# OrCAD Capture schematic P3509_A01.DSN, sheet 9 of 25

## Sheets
9 0016_HDMI: size Custom
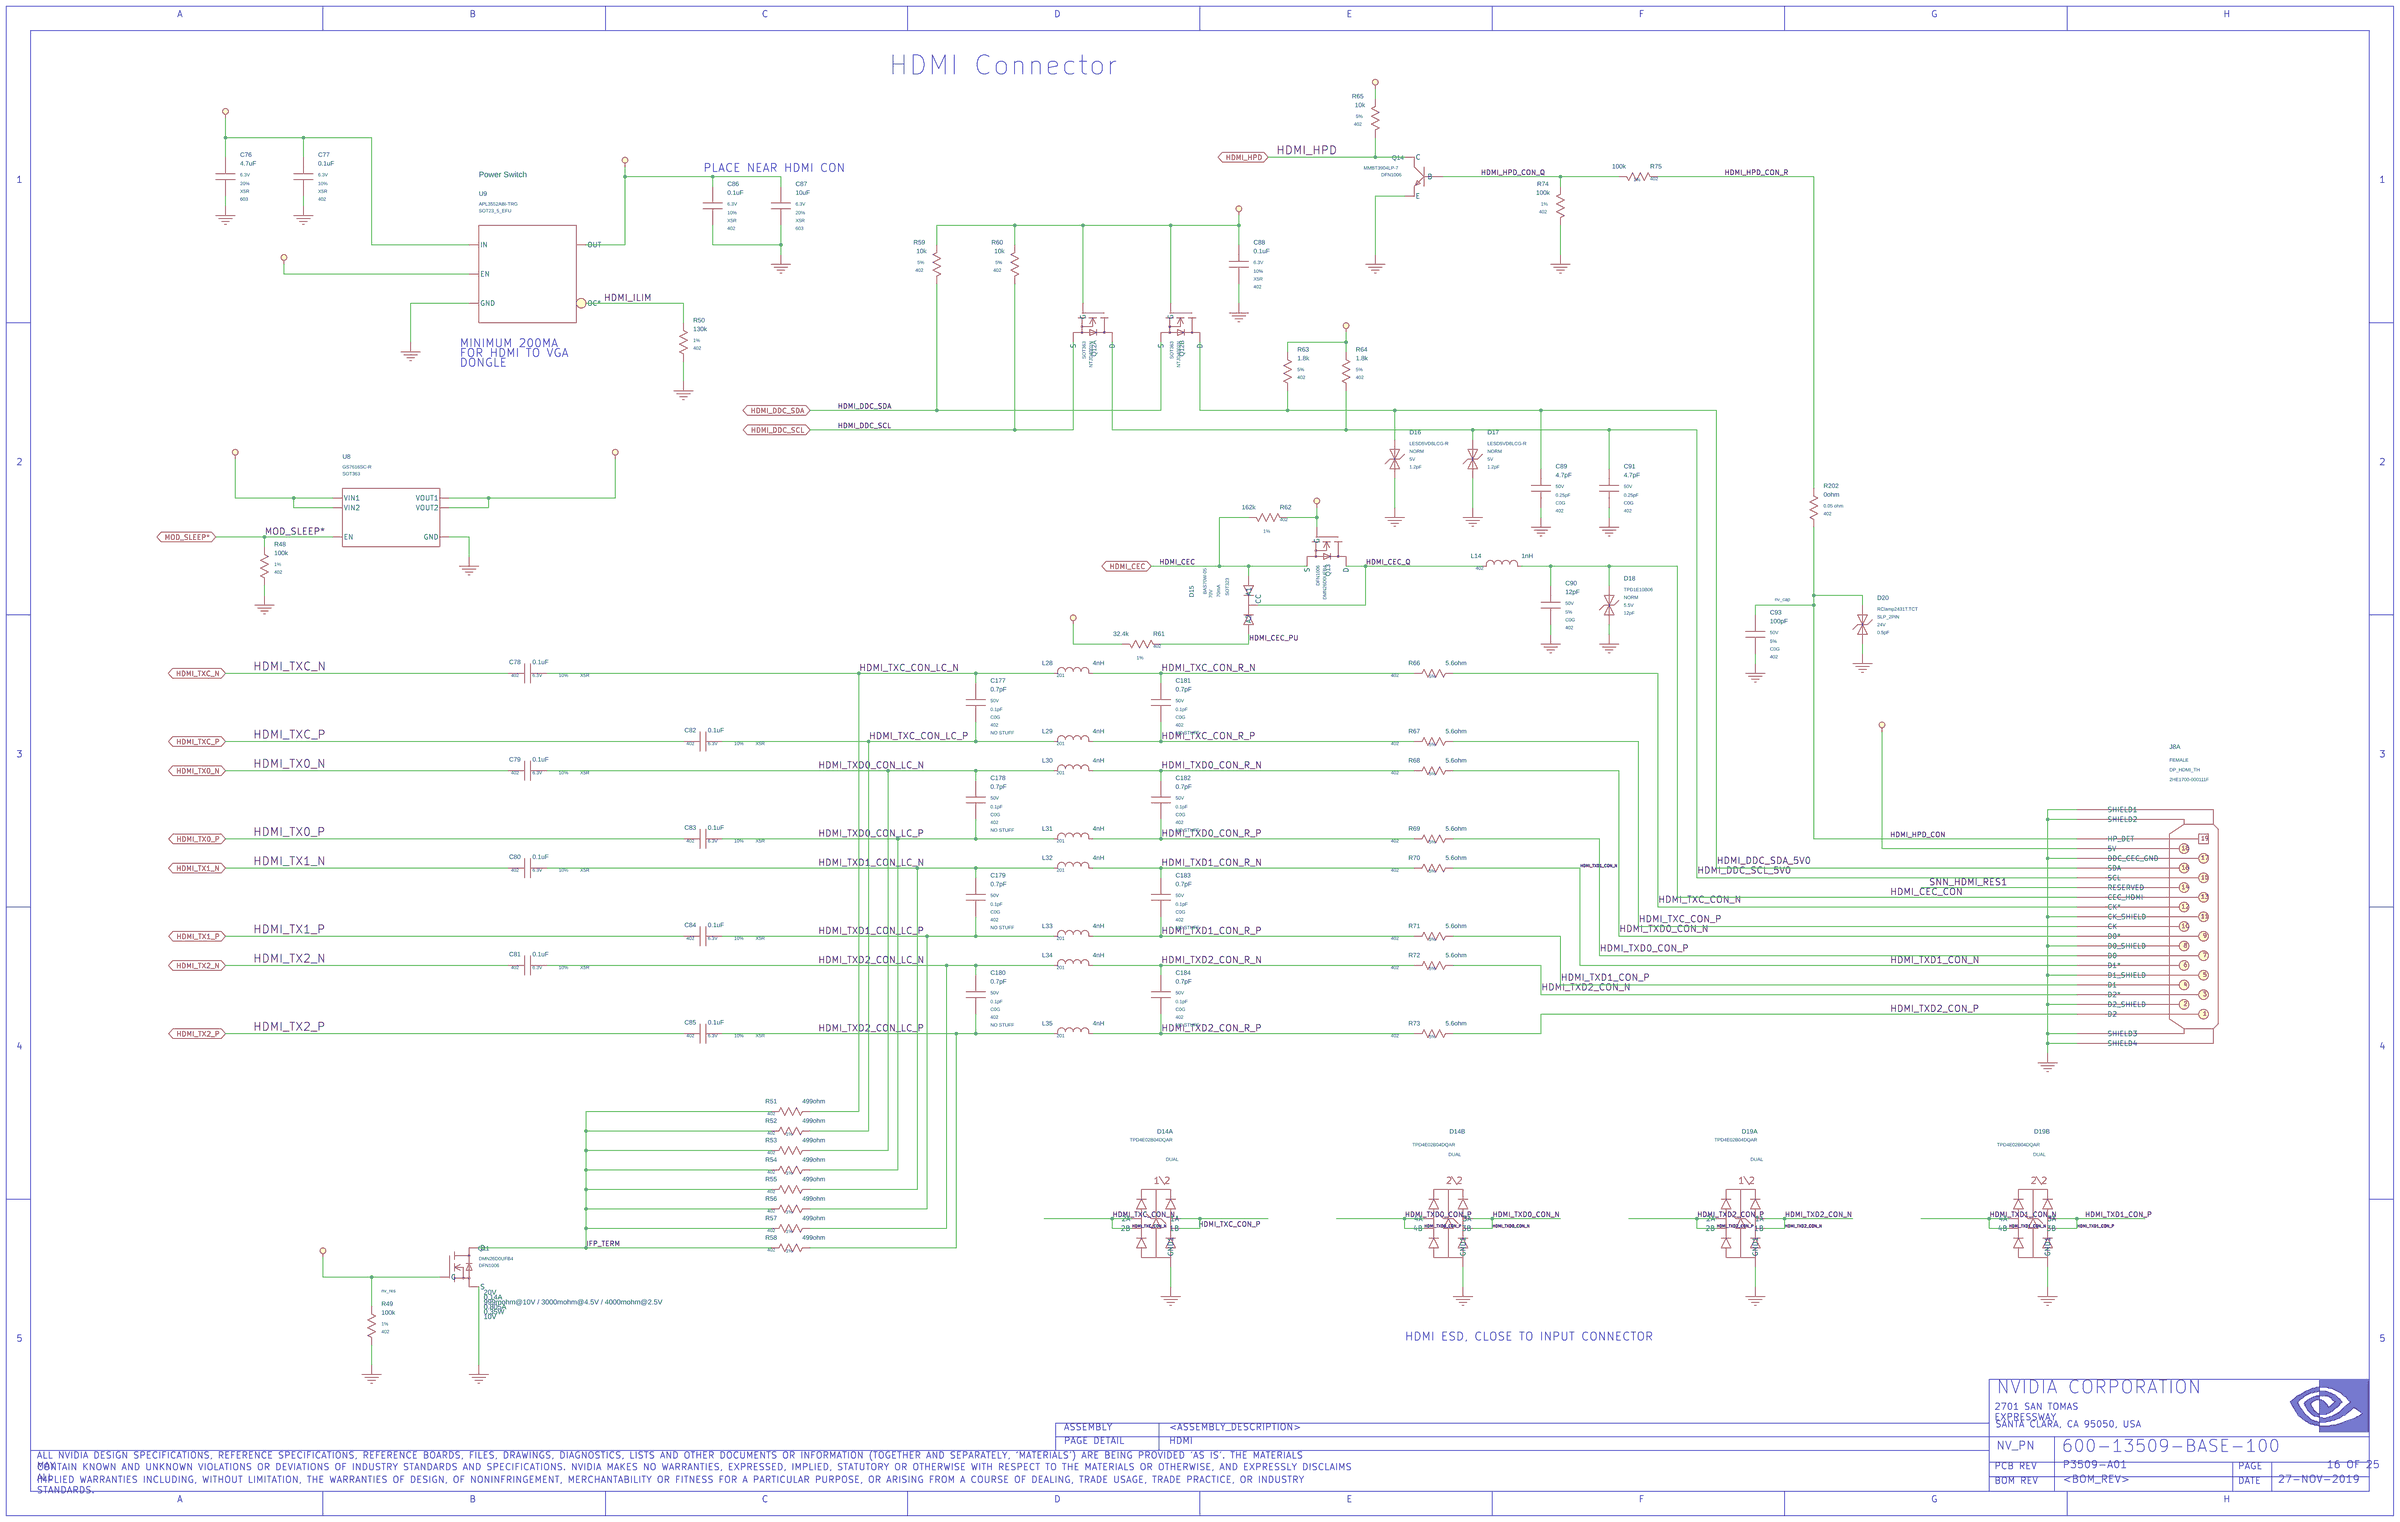
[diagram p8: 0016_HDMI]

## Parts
C76  4.7uF  [603]
C77  0.1uF  [402]
C78  0.1uF  [402]
C79  0.1uF  [402]
C80  0.1uF  [402]
C81  0.1uF  [402]
C82  0.1uF  [402]
C83  0.1uF  [402]
C84  0.1uF  [402]
C85  0.1uF  [402]
C86  0.1uF  [402]
C87  10uF  [603]
C88  0.1uF  [402]
C89  4.7pF  [402]
C90  12pF  [402]
C91  4.7pF  [402]
C93  100pF  [402]
C177  0.7pF  [402]
C178  0.7pF  [402]
C179  0.7pF  [402]
C180  0.7pF  [402]
C181  0.7pF  [402]
C182  0.7pF  [402]
C183  0.7pF  [402]
C184  0.7pF  [402]
D14  D_ESD_DIFFPAIR  [TSLP10_P050_025X010]  (sections A,B)
D15  D_3PIN_CC  [SOT323]
D16  D_ESD  [DIODE_SMD_010X060]
D17  D_ESD  [DIODE_SMD_010X060]
D18  D_ESD  [DIODE_SMD_010X060]
D19  D_ESD_DIFFPAIR  [TSLP10_P050_025X010]  (sections A,B)
D20  D_ESD  [DIODE_SMD_010X060]
J8  CON_HDMI_DISPLAYPORT  [CON_HDMI_019_DP_020_TH_RA_F_181X180_B]  (sections A,B)
L14  1nH  [IND_SMD_0402]
L28  4nH  [IND_SMD_0201_B]
L29  4nH  [IND_SMD_0201_B]
L30  4nH  [IND_SMD_0201_B]
L31  4nH  [IND_SMD_0201_B]
L32  4nH  [IND_SMD_0201_B]
L33  4nH  [IND_SMD_0201_B]
L34  4nH  [IND_SMD_0201_B]
L35  4nH  [IND_SMD_0201_B]
Q11  Q_FET_N_ENH  [DFET_003_SMD_010X006_B]
Q12  Q_FET_N_ENH  [SC70_6]  (sections A,B)
Q13  Q_FET_N_ENH  [DFET_003_SMD_010X006_B]
Q14  Q_NPN  [DFET_003_SMD_010X006_B]
R48  100k  [402]
R49  100k  [402]
R50  130k  [402]
R51  499ohm  [402]
R52  499ohm  [402]
R53  499ohm  [402]
R54  499ohm  [402]
R55  499ohm  [402]
R56  499ohm  [402]
R57  499ohm  [402]
R58  499ohm  [402]
R59  10k  [402]
R60  10k  [402]
R61  32.4k  [402]
R62  162k  [402]
R63  1.8k  [402]
R64  1.8k  [402]
R65  10k  [402]
R66  5.6ohm  [402]
R67  5.6ohm  [402]
R68  5.6ohm  [402]
R69  5.6ohm  [402]
R70  5.6ohm  [402]
R71  5.6ohm  [402]
R72  5.6ohm  [402]
R73  5.6ohm  [402]
R74  100k  [402]
R75  100k  [402]
R202  0ohm  [402]
U8  U_SW_LOAD  [SC70_6]
U9  U_PWR_SW_UL  [SOT23_5]

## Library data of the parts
C76 = C#1_v2: ASSEMBLY: HDMI; CDS_LIB: discrete; CDS_PART_NAME: C_0603-4.7UF,X5R,20%,6.3V,032-0886-000; CDS_PHYS_PART_NAME: C_0603-4.7UF,X5R,20%,6.3V,032-0886-000-032-0886-000,4.7UF; CDS_SEC: 1; CHIPS_PART_NAME: C; DEVICE_TYPENAME: C_0603-47UFX5R2063V032-0886-000-032-0886-00047UF; DRAWING: #NAME?; MAT: X5R; MAX_VOLTAGE: 6.3V; NV_PN: 032-0886-000; PATH: I95; PHYS_PAGE: 16; ROT: 0; SEC: 1; SIGNAL_MODEL: nv_cap; TOL: 20%; VER: 1; XY: (-11000,6750)
C77 = C#1_v2: ASSEMBLY: HDMI; CDS_LIB: discrete; CDS_PART_NAME: C_0402-0.1UF,X5R,10%,6.3V,039-0007-000; CDS_PHYS_PART_NAME: C_0402-0.1UF,X5R,10%,6.3V,039-0007-000-0.1UF,039-0007-000; CDS_SEC: 1; CHIPS_PART_NAME: C; DEVICE_TYPENAME: C_0402-01UFX5R1063V039-0007-000-01UF039-0007-000; DRAWING: #NAME?; ESL: N/A; ESR: N/A; MAT: X5R; MAX_VOLTAGE: 6.3V; NV_PN: 039-0007-000; PATH: I93; PHYS_PAGE: 16; ROT: 0; SEC: 1; SIGNAL_MODEL: nv_cap; TOL: 10%; VER: 1; XY: (-10600,6750)
C78 = C: ASSEMBLY: HDMI; CDS_LIB: discrete; CDS_PART_NAME: C_0402-0.1UF,X5R,10%,6.3V,039-0007-000; CDS_PHYS_PART_NAME: C_0402-0.1UF,X5R,10%,6.3V,039-0007-000-0.1UF,039-0007-000; CDS_SEC: 1; DEVICE_TYPENAME: C_0402-01UFX5R1063V039-0007-000-01UF039-0007-000; DRAWING: #NAME?; MAT: X5R; MAX_VOLTAGE: 6.3V; NO_XNET: 1; NV_PN: 039-0007-000; PATH: I103; PHYS_PAGE: 16; ROT: 0; SEC: 1; SIGNAL_MODEL: nv_cap; TOL: 10%; VER: 2; XY: (-9450,4200)
C79 = C: ASSEMBLY: HDMI; CDS_LIB: discrete; CDS_PART_NAME: C_0402-0.1UF,X5R,10%,6.3V,039-0007-000; CDS_PHYS_PART_NAME: C_0402-0.1UF,X5R,10%,6.3V,039-0007-000-0.1UF,039-0007-000; CDS_SEC: 1; DEVICE_TYPENAME: C_0402-01UFX5R1063V039-0007-000-01UF039-0007-000; DRAWING: #NAME?; MAT: X5R; MAX_VOLTAGE: 6.3V; NO_XNET: 1; NV_PN: 039-0007-000; PATH: I108; PHYS_PAGE: 16; ROT: 0; SEC: 1; SIGNAL_MODEL: nv_cap; TOL: 10%; VER: 2; XY: (-9450,3700)
C80 = C: ASSEMBLY: HDMI; CDS_LIB: discrete; CDS_PART_NAME: C_0402-0.1UF,X5R,10%,6.3V,039-0007-000; CDS_PHYS_PART_NAME: C_0402-0.1UF,X5R,10%,6.3V,039-0007-000-0.1UF,039-0007-000; CDS_SEC: 1; DEVICE_TYPENAME: C_0402-01UFX5R1063V039-0007-000-01UF039-0007-000; DRAWING: #NAME?; MAT: X5R; MAX_VOLTAGE: 6.3V; NO_XNET: 1; NV_PN: 039-0007-000; PATH: I109; PHYS_PAGE: 16; ROT: 0; SEC: 1; SIGNAL_MODEL: nv_cap; TOL: 10%; VER: 2; XY: (-9450,3200)
C81 = C: ASSEMBLY: HDMI; CDS_LIB: discrete; CDS_PART_NAME: C_0402-0.1UF,X5R,10%,6.3V,039-0007-000; CDS_PHYS_PART_NAME: C_0402-0.1UF,X5R,10%,6.3V,039-0007-000-0.1UF,039-0007-000; CDS_SEC: 1; DEVICE_TYPENAME: C_0402-01UFX5R1063V039-0007-000-01UF039-0007-000; DRAWING: #NAME?; MAT: X5R; MAX_VOLTAGE: 6.3V; NO_XNET: 1; NV_PN: 039-0007-000; PATH: I110; PHYS_PAGE: 16; ROT: 0; SEC: 1; SIGNAL_MODEL: nv_cap; TOL: 10%; VER: 2; XY: (-9450,2700)
C82 = C: ASSEMBLY: HDMI; CDS_LIB: discrete; CDS_PART_NAME: C_0402-0.1UF,X5R,10%,6.3V,039-0007-000; CDS_PHYS_PART_NAME: C_0402-0.1UF,X5R,10%,6.3V,039-0007-000-0.1UF,039-0007-000; CDS_SEC: 1; DEVICE_TYPENAME: C_0402-01UFX5R1063V039-0007-000-01UF039-0007-000; DRAWING: #NAME?; MAT: X5R; MAX_VOLTAGE: 6.3V; NO_XNET: 1; NV_PN: 039-0007-000; PATH: I104; PHYS_PAGE: 16; ROT: 0; SEC: 1; SIGNAL_MODEL: nv_cap; TOL: 10%; VER: 2; XY: (-8550,3850)
C83 = C: ASSEMBLY: HDMI; CDS_LIB: discrete; CDS_PART_NAME: C_0402-0.1UF,X5R,10%,6.3V,039-0007-000; CDS_PHYS_PART_NAME: C_0402-0.1UF,X5R,10%,6.3V,039-0007-000-0.1UF,039-0007-000; CDS_SEC: 1; DEVICE_TYPENAME: C_0402-01UFX5R1063V039-0007-000-01UF039-0007-000; DRAWING: #NAME?; MAT: X5R; MAX_VOLTAGE: 6.3V; NO_XNET: 1; NV_PN: 039-0007-000; PATH: I105; PHYS_PAGE: 16; ROT: 0; SEC: 1; SIGNAL_MODEL: nv_cap; TOL: 10%; VER: 2; XY: (-8550,3350)
C84 = C: ASSEMBLY: HDMI; CDS_LIB: discrete; CDS_PART_NAME: C_0402-0.1UF,X5R,10%,6.3V,039-0007-000; CDS_PHYS_PART_NAME: C_0402-0.1UF,X5R,10%,6.3V,039-0007-000-0.1UF,039-0007-000; CDS_SEC: 1; DEVICE_TYPENAME: C_0402-01UFX5R1063V039-0007-000-01UF039-0007-000; DRAWING: #NAME?; MAT: X5R; MAX_VOLTAGE: 6.3V; NO_XNET: 1; NV_PN: 039-0007-000; PATH: I106; PHYS_PAGE: 16; ROT: 0; SEC: 1; SIGNAL_MODEL: nv_cap; TOL: 10%; VER: 2; XY: (-8550,2850)
C85 = C: ASSEMBLY: HDMI; CDS_LIB: discrete; CDS_PART_NAME: C_0402-0.1UF,X5R,10%,6.3V,039-0007-000; CDS_PHYS_PART_NAME: C_0402-0.1UF,X5R,10%,6.3V,039-0007-000-0.1UF,039-0007-000; CDS_SEC: 1; DEVICE_TYPENAME: C_0402-01UFX5R1063V039-0007-000-01UF039-0007-000; DRAWING: #NAME?; MAT: X5R; MAX_VOLTAGE: 6.3V; NO_XNET: 1; NV_PN: 039-0007-000; PATH: I107; PHYS_PAGE: 16; ROT: 0; SEC: 1; SIGNAL_MODEL: nv_cap; TOL: 10%; VER: 2; XY: (-8550,2350)
C86 = C#1_v2: ASSEMBLY: HDMI; CDS_LIB: discrete; CDS_PART_NAME: C_0402-0.1UF,X5R,10%,6.3V,039-0007-000; CDS_PHYS_PART_NAME: C_0402-0.1UF,X5R,10%,6.3V,039-0007-000-0.1UF,039-0007-000; CDS_SEC: 1; CHIPS_PART_NAME: C; DEVICE_TYPENAME: C_0402-01UFX5R1063V039-0007-000-01UF039-0007-000; DRAWING: #NAME?; ESL: N/A; ESR: N/A; MAT: X5R; MAX_VOLTAGE: 6.3V; NV_PN: 039-0007-000; PATH: I85; PHYS_PAGE: 16; ROT: 0; SEC: 1; SIGNAL_MODEL: nv_cap; TOL: 10%; VER: 1; XY: (-8500,6600)
C87 = C#1_v2: ASSEMBLY: HDMI; CDS_LIB: discrete; CDS_PART_NAME: C_0603-10UF,X5R,20%,6.3V,039-0135-000; CDS_PHYS_PART_NAME: C_0603-10UF,X5R,20%,6.3V,039-0135-000-039-0135-000,10UF; CDS_SEC: 1; CHIPS_PART_NAME: C; DEVICE_TYPENAME: C_0603-10UFX5R2063V039-0135-000-039-0135-00010UF; DRAWING: #NAME?; ESL: N/A; ESR: N/A; MAT: X5R; MAX_VOLTAGE: 6.3V; NV_PN: 039-0135-000; PATH: I56; PHYS_PAGE: 16; ROT: 0; SEC: 1; SIGNAL_MODEL: nv_cap; TOL: 20%; VER: 1; XY: (-8150,6600)
C88 = C#1_v2: ASSEMBLY: HDMI; CDS_LIB: discrete; CDS_PART_NAME: C_0402-0.1UF,X5R,10%,6.3V,039-0007-000; CDS_PHYS_PART_NAME: C_0402-0.1UF,X5R,10%,6.3V,039-0007-000-0.1UF,039-0007-000; CDS_SEC: 1; CHIPS_PART_NAME: C; DEVICE_TYPENAME: C_0402-01UFX5R1063V039-0007-000-01UF039-0007-000; DRAWING: #NAME?; ESL: N/A; ESR: N/A; MAT: X5R; MAX_VOLTAGE: 6.3V; NV_PN: 039-0007-000; PATH: I37; PHYS_PAGE: 16; ROT: 0; SEC: 1; SIGNAL_MODEL: nv_cap; TOL: 10%; VER: 1; XY: (-5800,6300)
C89 = C#1_v2: ASSEMBLY: HDMI; CDS_LIB: discrete; CDS_PART_NAME: C_0402-4.7PF,C0G,0.25PF,50V,035-0031-000; CDS_PHYS_PART_NAME: C_0402-4.7PF,C0G,0.25PF,50V,035-0031-000-035-0031-000,4.7PF; CDS_SEC: 1; CHIPS_PART_NAME: C; DEVICE_TYPENAME: C_0402-47PFC0G025PF50V035-0031-000-035-0031-00047PF; DRAWING: #NAME?; MAT: C0G; MAX_VOLTAGE: 50V; NV_PN: 035-0031-000; PATH: I19; PHYS_PAGE: 16; ROT: 0; SEC: 1; SIGNAL_MODEL: nv_cap; TOL: 0.25pF; VER: 1; XY: (-4250,5150)
C90 = C#1_v2: ASSEMBLY: HDMI; CDS_LIB: discrete; CDS_PART_NAME: C_0402-12PF,C0G,5%,50V,035-0014-000; CDS_PHYS_PART_NAME: C_0402-12PF,C0G,5%,50V,035-0014-000-035-0014-000,12PF; CDS_SEC: 1; CHIPS_PART_NAME: C; DEVICE_TYPENAME: C_0402-12PFC0G550V035-0014-000-035-0014-00012PF; DRAWING: #NAME?; ESL: N/A; ESR: N/A; MAT: C0G; MAX_VOLTAGE: 50V; NV_PN: 035-0014-000; PATH: I23; PHYS_PAGE: 16; ROT: 0; SEC: 1; SIGNAL_MODEL: nv_cap; TOL: 5%; VER: 1; XY: (-4200,4550)
C91 = C#1_v2: ASSEMBLY: HDMI; CDS_LIB: discrete; CDS_PART_NAME: C_0402-4.7PF,C0G,0.25PF,50V,035-0031-000; CDS_PHYS_PART_NAME: C_0402-4.7PF,C0G,0.25PF,50V,035-0031-000-035-0031-000,4.7PF; CDS_SEC: 1; CHIPS_PART_NAME: C; DEVICE_TYPENAME: C_0402-47PFC0G025PF50V035-0031-000-035-0031-00047PF; DRAWING: #NAME?; MAT: C0G; MAX_VOLTAGE: 50V; NV_PN: 035-0031-000; PATH: I18; PHYS_PAGE: 16; ROT: 0; SEC: 1; SIGNAL_MODEL: nv_cap; TOL: 0.25pF; VER: 1; XY: (-3900,5150)
C93 = C#1_v2: ASSEMBLY: HDMI; CDS_LIB: discrete; CDS_PART_NAME: C_0402-100PF,C0G,5%,50V,035-0012-000; CDS_PHYS_PART_NAME: C_0402-100PF,C0G,5%,50V,035-0012-000-035-0012-000,100PF; CDS_SEC: 1; CHIPS_PART_NAME: C; DEVICE_TYPENAME: C_0402-100PFC0G550V035-0012-000-035-0012-000100PF; DRAWING: #NAME?; MAT: C0G; MAX_VOLTAGE: 50V; NV_PN: 035-0012-000; PATH: I16; PHYS_PAGE: 16; ROT: 0; SEC: 1; SIGNAL_MODEL: nv_cap; TOL: 5%; VER: 1; XY: (-3150,4400)
C177 = C#1_v2: ASSEMBLY: HDMI; CDS_LIB: discrete; CDS_PART_NAME: C_0402-0.7PF,C0G,0.1PF,50V,035-0203-000; CDS_PHYS_PART_NAME: C_0402-0.7PF,C0G,0.1PF,50V,035-0203-000-0.7PF,035-0203-000; CDS_SEC: 1; CHIPS_PART_NAME: C; DEVICE_TYPENAME: C_0402-07PFC0G01PF50V035-0203-000-07PF035-0203-000; DRAWING: #NAME?; MAT: C0G; MAX_VOLTAGE: 50V; NV_PN: 035-0203-000; PATH: I135; PHYS_PAGE: 16; ROT: 0; SEC: 1; SKU: NO STUFF; TOL: 0.1pF; VER: 1; XY: (-7150,4050)
C178 = C#1_v2: ASSEMBLY: HDMI; CDS_LIB: discrete; CDS_PART_NAME: C_0402-0.7PF,C0G,0.1PF,50V,035-0203-000; CDS_PHYS_PART_NAME: C_0402-0.7PF,C0G,0.1PF,50V,035-0203-000-0.7PF,035-0203-000; CDS_SEC: 1; CHIPS_PART_NAME: C; DEVICE_TYPENAME: C_0402-07PFC0G01PF50V035-0203-000-07PF035-0203-000; DRAWING: #NAME?; MAT: C0G; MAX_VOLTAGE: 50V; NV_PN: 035-0203-000; PATH: I136; PHYS_PAGE: 16; ROT: 0; SEC: 1; SKU: NO STUFF; TOL: 0.1pF; VER: 1; XY: (-7150,3550)
C179 = C#1_v2: ASSEMBLY: HDMI; CDS_LIB: discrete; CDS_PART_NAME: C_0402-0.7PF,C0G,0.1PF,50V,035-0203-000; CDS_PHYS_PART_NAME: C_0402-0.7PF,C0G,0.1PF,50V,035-0203-000-0.7PF,035-0203-000; CDS_SEC: 1; CHIPS_PART_NAME: C; DEVICE_TYPENAME: C_0402-07PFC0G01PF50V035-0203-000-07PF035-0203-000; DRAWING: #NAME?; MAT: C0G; MAX_VOLTAGE: 50V; NV_PN: 035-0203-000; PATH: I138; PHYS_PAGE: 16; ROT: 0; SEC: 1; SKU: NO STUFF; TOL: 0.1pF; VER: 1; XY: (-7150,3050)
C180 = C#1_v2: ASSEMBLY: HDMI; CDS_LIB: discrete; CDS_PART_NAME: C_0402-0.7PF,C0G,0.1PF,50V,035-0203-000; CDS_PHYS_PART_NAME: C_0402-0.7PF,C0G,0.1PF,50V,035-0203-000-0.7PF,035-0203-000; CDS_SEC: 1; CHIPS_PART_NAME: C; DEVICE_TYPENAME: C_0402-07PFC0G01PF50V035-0203-000-07PF035-0203-000; DRAWING: #NAME?; MAT: C0G; MAX_VOLTAGE: 50V; NV_PN: 035-0203-000; PATH: I140; PHYS_PAGE: 16; ROT: 0; SEC: 1; SKU: NO STUFF; TOL: 0.1pF; VER: 1; XY: (-7150,2550)
C181 = C#1_v2: ASSEMBLY: HDMI; CDS_LIB: discrete; CDS_PART_NAME: C_0402-0.7PF,C0G,0.1PF,50V,035-0203-000; CDS_PHYS_PART_NAME: C_0402-0.7PF,C0G,0.1PF,50V,035-0203-000-0.7PF,035-0203-000; CDS_SEC: 1; CHIPS_PART_NAME: C; DEVICE_TYPENAME: C_0402-07PFC0G01PF50V035-0203-000-07PF035-0203-000; DRAWING: #NAME?; MAT: C0G; MAX_VOLTAGE: 50V; NV_PN: 035-0203-000; PATH: I126; PHYS_PAGE: 16; ROT: 0; SEC: 1; SKU: NO STUFF; TOL: 0.1pF; VER: 1; XY: (-6200,4050)
C182 = C#1_v2: ASSEMBLY: HDMI; CDS_LIB: discrete; CDS_PART_NAME: C_0402-0.7PF,C0G,0.1PF,50V,035-0203-000; CDS_PHYS_PART_NAME: C_0402-0.7PF,C0G,0.1PF,50V,035-0203-000-0.7PF,035-0203-000; CDS_SEC: 1; CHIPS_PART_NAME: C; DEVICE_TYPENAME: C_0402-07PFC0G01PF50V035-0203-000-07PF035-0203-000; DRAWING: #NAME?; MAT: C0G; MAX_VOLTAGE: 50V; NV_PN: 035-0203-000; PATH: I137; PHYS_PAGE: 16; ROT: 0; SEC: 1; SKU: NO STUFF; TOL: 0.1pF; VER: 1; XY: (-6200,3550)
C183 = C#1_v2: ASSEMBLY: HDMI; CDS_LIB: discrete; CDS_PART_NAME: C_0402-0.7PF,C0G,0.1PF,50V,035-0203-000; CDS_PHYS_PART_NAME: C_0402-0.7PF,C0G,0.1PF,50V,035-0203-000-0.7PF,035-0203-000; CDS_SEC: 1; CHIPS_PART_NAME: C; DEVICE_TYPENAME: C_0402-07PFC0G01PF50V035-0203-000-07PF035-0203-000; DRAWING: #NAME?; MAT: C0G; MAX_VOLTAGE: 50V; NV_PN: 035-0203-000; PATH: I139; PHYS_PAGE: 16; ROT: 0; SEC: 1; SKU: NO STUFF; TOL: 0.1pF; VER: 1; XY: (-6200,3050)
C184 = C#1_v2: ASSEMBLY: HDMI; CDS_LIB: discrete; CDS_PART_NAME: C_0402-0.7PF,C0G,0.1PF,50V,035-0203-000; CDS_PHYS_PART_NAME: C_0402-0.7PF,C0G,0.1PF,50V,035-0203-000-0.7PF,035-0203-000; CDS_SEC: 1; CHIPS_PART_NAME: C; DEVICE_TYPENAME: C_0402-07PFC0G01PF50V035-0203-000-07PF035-0203-000; DRAWING: #NAME?; MAT: C0G; MAX_VOLTAGE: 50V; NV_PN: 035-0203-000; PATH: I141; PHYS_PAGE: 16; ROT: 0; SEC: 1; SKU: NO STUFF; TOL: 0.1pF; VER: 1; XY: (-6200,2550)
D14 = D_ESD_DIFFPAIR: ASSEMBLY: HDMI; BREAKDOWN_VOLTAGE_MIN_TYP: 6.7V; CAPACITANCE_MAX_TYP: 0.37pF; CDS_LIB: discrete; CDS_PART_NAME: D_ESD_DIFFPAIR_DUAL-TPD4E02B04DQAR,2 DIFFPAIR,BI-DIRECTIONAL,6V,0.01UA,6.7V,8V@40A,0.37PF,090-0296-000; CDS_PHYS_PART_NAME: D_ESD_DIFFPAIR_DUAL-TPD4E02B04DQAR,2 DIFFPAIR,BI-DIRECTIONAL,6V,0.01UA,6.7V,8V@40A,0.37PF,090-0296-000-090-0296-000; CDS_SEC: 1; CLAMPING_VOLTAGE: 8V@40A; CONFIGURATION: 2 Diffpair; CaptureCellPackProp: D_ESD_DIFFPAIRA; DEVICE_TYPENAME: D_ESD_DIFFPAIR_DUAL-TPD4E02B04DQAR2DIFFPAIRBI-DIRECTIONAL6V001UA67V8V40A037PF090-0296-000-090-0296-000; DRAWING: #NAME?; MAX_REVERSE_LEAKAGE_CURRENT: 0.01uA; MAX_REVERSE_VOLTAGE: 6V; NV_NAME: TPD4E02B04DQAR; NV_PN: 090-0296-000; PACK_TYPE: DUAL; PATH: I74; PHYS_PAGE: 16; POLARITY: Bi-Directional; ROT: 2; SEC: 1; VER: 1; XY: (-6200,1400)
D15 = D_3PIN_CC#1: ASSEMBLY: HDMI; CDS_LIB: discrete; CDS_PART_NAME: D_3PIN_CC_SOT323-BAS70W-05,1 PAIR - COMMON CATHODE,70V,0.1A,1V@15MA,70MA,091-0023-000; CDS_PHYS_PART_NAME: D_3PIN_CC_SOT323-BAS70W-05,1 PAIR - COMMON CATHODE,70V,0.1A,1V@15MA,70MA,091-0023-000-091-0023-000; CDS_SEC: 1; CONFIGURATION: 1 Pair - Common Cathode; CONTINUOUS_CURRENT: 70mA; DEVICE_TYPENAME: D_3PIN_CC_SOT323-BAS70W-051PAIR-COMMONCATHODE70V01A1V15MA70MA091-0023-000-091-0023-000; DRAWING: #NAME?; FORWARD_VOLTAGE: 1V@15mA; MAX_CURRENT: 0.1A; MAX_VOLTAGE: 70V; NV_NAME: BAS70W-05; NV_PN: 091-0023-000; PATH: I52; PHYS_PAGE: 16; ROT: 1; SEC: 1; VER: 4; XY: (-5750,4550)
D16 = D_ESD: ASSEMBLY: HDMI; BREAKDOWN_VOLTAGE_MIN_TYP: 5.5V; CAPACITANCE_MAX_TYP: 1.2pF; CDS_LIB: discrete; CDS_PART_NAME: D_ESD_NORM-LESD5VD8LCG-R,1 LINE,BI-DIRECTIONAL,5V,0.05UA,5.5V,10V@2A,1.2PF,090-0172-000; CDS_PHYS_PART_NAME: D_ESD_NORM-LESD5VD8LCG-R,1 LINE,BI-DIRECTIONAL,5V,0.05UA,5.5V,10V@2A,1.2PF,090-0172-000-090-0172-000; CDS_SEC: 1; CLAMPING_VOLTAGE: 10V@2A; CONFIGURATION: 1 Line; DEVICE_TYPENAME: D_ESD_NORM-LESD5VD8LCG-R1LINEBI-DIRECTIONAL5V005UA55V10V2A12PF090-0172-000-090-0172-000; DRAWING: #NAME?; MAX_REVERSE_LEAKAGE_CURRENT: 0.05uA; MAX_REVERSE_VOLTAGE: 5V; NV_NAME: LESD5VD8LCG-R; NV_PN: 090-0172-000; PACK_TYPE: NORM; PATH: I41; PHYS_PAGE: 16; POLARITY: Bi-Directional; ROT: 0; SEC: 1; VER: 2; XY: (-5000,5300)
D17 = D_ESD: ASSEMBLY: HDMI; BREAKDOWN_VOLTAGE_MIN_TYP: 5.5V; CAPACITANCE_MAX_TYP: 1.2pF; CDS_LIB: discrete; CDS_PART_NAME: D_ESD_NORM-LESD5VD8LCG-R,1 LINE,BI-DIRECTIONAL,5V,0.05UA,5.5V,10V@2A,1.2PF,090-0172-000; CDS_PHYS_PART_NAME: D_ESD_NORM-LESD5VD8LCG-R,1 LINE,BI-DIRECTIONAL,5V,0.05UA,5.5V,10V@2A,1.2PF,090-0172-000-090-0172-000; CDS_SEC: 1; CLAMPING_VOLTAGE: 10V@2A; CONFIGURATION: 1 Line; DEVICE_TYPENAME: D_ESD_NORM-LESD5VD8LCG-R1LINEBI-DIRECTIONAL5V005UA55V10V2A12PF090-0172-000-090-0172-000; DRAWING: #NAME?; MAX_REVERSE_LEAKAGE_CURRENT: 0.05uA; MAX_REVERSE_VOLTAGE: 5V; NV_NAME: LESD5VD8LCG-R; NV_PN: 090-0172-000; PACK_TYPE: NORM; PATH: I38; PHYS_PAGE: 16; POLARITY: Bi-Directional; ROT: 0; SEC: 1; VER: 2; XY: (-4600,5300)
D18 = D_ESD: ASSEMBLY: HDMI; BREAKDOWN_VOLTAGE_MIN_TYP: 6V; CAPACITANCE_MAX_TYP: 12pF; CDS_LIB: discrete; CDS_PART_NAME: D_ESD_NORM-TPD1E10B06,1 LINE,BI-DIRECTIONAL,5.5V,0.1UA,6V,10V@1A,12PF,090-0243-000; CDS_PHYS_PART_NAME: D_ESD_NORM-TPD1E10B06,1 LINE,BI-DIRECTIONAL,5.5V,0.1UA,6V,10V@1A,12PF,090-0243-000-090-0243-000; CDS_SEC: 1; CLAMPING_VOLTAGE: 10V@1A; CONFIGURATION: 1 Line; DEVICE_TYPENAME: D_ESD_NORM-TPD1E10B061LINEBI-DIRECTIONAL55V01UA6V10V1A12PF090-0243-000-090-0243-000; DRAWING: #NAME?; MAX_REVERSE_LEAKAGE_CURRENT: 0.1uA; MAX_REVERSE_VOLTAGE: 5.5V; NV_NAME: TPD1E10B06; NV_PN: 090-0243-000; PACK_TYPE: NORM; PATH: I22; PHYS_PAGE: 16; POLARITY: Bi-Directional; ROT: 0; SEC: 1; VER: 2; XY: (-3900,4550)
D19 = D_ESD_DIFFPAIR: ASSEMBLY: HDMI; BREAKDOWN_VOLTAGE_MIN_TYP: 6.7V; CAPACITANCE_MAX_TYP: 0.37pF; CDS_LIB: discrete; CDS_PART_NAME: D_ESD_DIFFPAIR_DUAL-TPD4E02B04DQAR,2 DIFFPAIR,BI-DIRECTIONAL,6V,0.01UA,6.7V,8V@40A,0.37PF,090-0296-000; CDS_PHYS_PART_NAME: D_ESD_DIFFPAIR_DUAL-TPD4E02B04DQAR,2 DIFFPAIR,BI-DIRECTIONAL,6V,0.01UA,6.7V,8V@40A,0.37PF,090-0296-000-090-0296-000; CDS_SEC: 2; CLAMPING_VOLTAGE: 8V@40A; CONFIGURATION: 2 Diffpair; CaptureCellPackProp: D_ESD_DIFFPAIRB; DEVICE_TYPENAME: D_ESD_DIFFPAIR_DUAL-TPD4E02B04DQAR2DIFFPAIRBI-DIRECTIONAL6V001UA67V8V40A037PF090-0296-000-090-0296-000; DRAWING: #NAME?; MAX_REVERSE_LEAKAGE_CURRENT: 0.01uA; MAX_REVERSE_VOLTAGE: 6V; NV_NAME: TPD4E02B04DQAR; NV_PN: 090-0296-000; PACK_TYPE: DUAL; PATH: I3; PHYS_PAGE: 16; POLARITY: Bi-Directional; ROT: 2; SEC: 2; VER: 2; XY: (-1700,1400)
D20 = D_ESD: ASSEMBLY: HDMI; BREAKDOWN_VOLTAGE_MIN_TYP: 26.7V; CAPACITANCE_MAX_TYP: 0.5pF; CDS_LIB: discrete; CDS_PART_NAME: D_ESD_SLP_2PIN-RCLAMP2431T.TCT,1 LINE,BI-DIRECTIONAL,24V,0.1UA,26.7V,45V@1A,0.5PF,090-0337-000; CDS_PHYS_PART_NAME: D_ESD_SLP_2PIN-RCLAMP2431T.TCT,1 LINE,BI-DIRECTIONAL,24V,0.1UA,26.7V,45V@1A,0.5PF,090-0337-000-090-0337-000; CDS_SEC: 1; CLAMPING_VOLTAGE: 45V@1A; CONFIGURATION: 1 Line; DEVICE_TYPENAME: D_ESD_SLP_2PIN-RCLAMP2431TTCT1LINEBI-DIRECTIONAL24V01UA267V45V1A05PF090-0337-000-090-0337-000; DRAWING: #NAME?; MAX_REVERSE_LEAKAGE_CURRENT: 0.1uA; MAX_REVERSE_VOLTAGE: 24V; NV_NAME: RClamp2431T.TCT; NV_PN: 090-0337-000; PACK_TYPE: SLP_2PIN; PATH: I14; PHYS_PAGE: 16; POLARITY: Bi-Directional; ROT: 0; SEC: 1; VER: 2; XY: (-2600,4450)
J8 = CON_HDMI_DISPLAYPORT: ANGLE: 90; ASSEMBLY: HDMI; CDS_LIB: electro_mechanic; CDS_PART_NAME: CON_HDMI_DISPLAYPORT_DP_HDMI_TH-2HE1700-000111F,FEMALE,1.4MM,90,YES,YES,YES,YES,YES,40 MV,500 MA,064-0374-000; CDS_PHYS_PART_NAME: CON_HDMI_DISPLAYPORT_DP_HDMI_TH-2HE1700-000111F,FEMALE,1.4MM,90,YES,YES,YES,YES,YES,40 MV,500 MA,064-0374-000-064-0374-000; CDS_SEC: 1; CaptureCellPackProp: CON_HDMI_DISPLAYPORTA; DEVICE_TYPENAME: CON_HDMI_DISPLAYPORT_DP_HDMI_TH-2HE1700-000111FFEMALE14MM90YESYESYESYESYES40MV500MA064-0374-000-064-0374-000; DRAWING: #NAME?; EMI_GROUND_TAB: YES; GENDER: FEMALE; LATCHING: YES; MAX_CURRENT: 500 mA; MAX_VOLTAGE: 40 mV; NV_NAME: 2HE1700-000111F; NV_PN: 064-0374-000; PACK_TYPE: DP_HDMI_TH; PATH: I25; PHYS_PAGE: 16; PITCH: 1.4mm; REFLOW: YES; ROT: 0; SEC: 1; SHIELDED: YES; SHROUDED: YES; VER: 1; XY: (-900,2900)
L14 = L: ASSEMBLY: HDMI; CDS_LIB: discrete; CDS_PART_NAME: L_0402-1NH,MULTI-LAYER,30%,0.4A,0.4A,0.07OHM,8@100MHZ,10GHZ,130-1041-000; CDS_PHYS_PART_NAME: L_0402-1NH,MULTI-LAYER,30%,0.4A,0.4A,0.07OHM,8@100MHZ,10GHZ,130-1041-000-130-1041-000,1NH; CDS_SEC: 1; CONTINUOUS_CURRENT: 0.4A; DC_RESISTANCE: 0.07ohm; DEVICE_TYPENAME: L_0402-1NHMULTI-LAYER3004A04A007OHM8100MHZ10GHZ130-1041-000-130-1041-0001NH; DRAWING: #NAME?; MAT: multi-layer; MAX_CURRENT: 0.4A; NV_PN: 130-1041-000; PACK_TYPE: 402; PATH: I43; PHYS_PAGE: 16; Q: 8@100MHz; ROT: 0; SEC: 1; SELF_RESONANCE_FREQ: 10GHz; SIGNAL_MODEL: nv_ind; TOL: 30%; VER: 1; XY: (-4450,4750)
L28 = L: ASSEMBLY: HDMI; CDS_LIB: discrete; CDS_PART_NAME: L_0201-4NH,CERAMIC,2.5%,0.35A,0.35A,0.4OHM,14@500MHZ,5.3GHZ,130-1369-000; CDS_PHYS_PART_NAME: L_0201-4NH,CERAMIC,2.5%,0.35A,0.35A,0.4OHM,14@500MHZ,5.3GHZ,130-1369-000-130-1369-000,4NH; CDS_SEC: 1; CONTINUOUS_CURRENT: 0.35A; DC_RESISTANCE: 0.4ohm; DEVICE_TYPENAME: L_0201-4NHCERAMIC25035A035A04OHM14500MHZ53GHZ130-1369-000-130-1369-0004NH; DRAWING: #NAME?; MAT: Ceramic; MAX_CURRENT: 0.35A; NV_PN: 130-1369-000; PACK_TYPE: 201; PATH: I127; PHYS_PAGE: 16; Q: 14@500MHz; ROT: 0; SEC: 1; SELF_RESONANCE_FREQ: 5.3GHz; TOL: 2.50%; VER: 1; XY: (-6650,4200)
L29 = L: ASSEMBLY: HDMI; CDS_LIB: discrete; CDS_PART_NAME: L_0201-4NH,CERAMIC,2.5%,0.35A,0.35A,0.4OHM,14@500MHZ,5.3GHZ,130-1369-000; CDS_PHYS_PART_NAME: L_0201-4NH,CERAMIC,2.5%,0.35A,0.35A,0.4OHM,14@500MHZ,5.3GHZ,130-1369-000-130-1369-000,4NH; CDS_SEC: 1; CONTINUOUS_CURRENT: 0.35A; DC_RESISTANCE: 0.4ohm; DEVICE_TYPENAME: L_0201-4NHCERAMIC25035A035A04OHM14500MHZ53GHZ130-1369-000-130-1369-0004NH; DRAWING: #NAME?; MAT: Ceramic; MAX_CURRENT: 0.35A; NV_PN: 130-1369-000; PACK_TYPE: 201; PATH: I128; PHYS_PAGE: 16; Q: 14@500MHz; ROT: 0; SEC: 1; SELF_RESONANCE_FREQ: 5.3GHz; TOL: 2.50%; VER: 1; XY: (-6650,3850)
L30 = L: ASSEMBLY: HDMI; CDS_LIB: discrete; CDS_PART_NAME: L_0201-4NH,CERAMIC,2.5%,0.35A,0.35A,0.4OHM,14@500MHZ,5.3GHZ,130-1369-000; CDS_PHYS_PART_NAME: L_0201-4NH,CERAMIC,2.5%,0.35A,0.35A,0.4OHM,14@500MHZ,5.3GHZ,130-1369-000-130-1369-000,4NH; CDS_SEC: 1; CONTINUOUS_CURRENT: 0.35A; DC_RESISTANCE: 0.4ohm; DEVICE_TYPENAME: L_0201-4NHCERAMIC25035A035A04OHM14500MHZ53GHZ130-1369-000-130-1369-0004NH; DRAWING: #NAME?; MAT: Ceramic; MAX_CURRENT: 0.35A; NV_PN: 130-1369-000; PACK_TYPE: 201; PATH: I129; PHYS_PAGE: 16; Q: 14@500MHz; ROT: 0; SEC: 1; SELF_RESONANCE_FREQ: 5.3GHz; TOL: 2.50%; VER: 1; XY: (-6650,3700)
L31 = L: ASSEMBLY: HDMI; CDS_LIB: discrete; CDS_PART_NAME: L_0201-4NH,CERAMIC,2.5%,0.35A,0.35A,0.4OHM,14@500MHZ,5.3GHZ,130-1369-000; CDS_PHYS_PART_NAME: L_0201-4NH,CERAMIC,2.5%,0.35A,0.35A,0.4OHM,14@500MHZ,5.3GHZ,130-1369-000-130-1369-000,4NH; CDS_SEC: 1; CONTINUOUS_CURRENT: 0.35A; DC_RESISTANCE: 0.4ohm; DEVICE_TYPENAME: L_0201-4NHCERAMIC25035A035A04OHM14500MHZ53GHZ130-1369-000-130-1369-0004NH; DRAWING: #NAME?; MAT: Ceramic; MAX_CURRENT: 0.35A; NV_PN: 130-1369-000; PACK_TYPE: 201; PATH: I130; PHYS_PAGE: 16; Q: 14@500MHz; ROT: 0; SEC: 1; SELF_RESONANCE_FREQ: 5.3GHz; TOL: 2.50%; VER: 1; XY: (-6650,3350)
L32 = L: ASSEMBLY: HDMI; CDS_LIB: discrete; CDS_PART_NAME: L_0201-4NH,CERAMIC,2.5%,0.35A,0.35A,0.4OHM,14@500MHZ,5.3GHZ,130-1369-000; CDS_PHYS_PART_NAME: L_0201-4NH,CERAMIC,2.5%,0.35A,0.35A,0.4OHM,14@500MHZ,5.3GHZ,130-1369-000-130-1369-000,4NH; CDS_SEC: 1; CONTINUOUS_CURRENT: 0.35A; DC_RESISTANCE: 0.4ohm; DEVICE_TYPENAME: L_0201-4NHCERAMIC25035A035A04OHM14500MHZ53GHZ130-1369-000-130-1369-0004NH; DRAWING: #NAME?; MAT: Ceramic; MAX_CURRENT: 0.35A; NV_PN: 130-1369-000; PACK_TYPE: 201; PATH: I131; PHYS_PAGE: 16; Q: 14@500MHz; ROT: 0; SEC: 1; SELF_RESONANCE_FREQ: 5.3GHz; TOL: 2.50%; VER: 1; XY: (-6650,3200)
L33 = L: ASSEMBLY: HDMI; CDS_LIB: discrete; CDS_PART_NAME: L_0201-4NH,CERAMIC,2.5%,0.35A,0.35A,0.4OHM,14@500MHZ,5.3GHZ,130-1369-000; CDS_PHYS_PART_NAME: L_0201-4NH,CERAMIC,2.5%,0.35A,0.35A,0.4OHM,14@500MHZ,5.3GHZ,130-1369-000-130-1369-000,4NH; CDS_SEC: 1; CONTINUOUS_CURRENT: 0.35A; DC_RESISTANCE: 0.4ohm; DEVICE_TYPENAME: L_0201-4NHCERAMIC25035A035A04OHM14500MHZ53GHZ130-1369-000-130-1369-0004NH; DRAWING: #NAME?; MAT: Ceramic; MAX_CURRENT: 0.35A; NV_PN: 130-1369-000; PACK_TYPE: 201; PATH: I132; PHYS_PAGE: 16; Q: 14@500MHz; ROT: 0; SEC: 1; SELF_RESONANCE_FREQ: 5.3GHz; TOL: 2.50%; VER: 1; XY: (-6650,2850)
L34 = L: ASSEMBLY: HDMI; CDS_LIB: discrete; CDS_PART_NAME: L_0201-4NH,CERAMIC,2.5%,0.35A,0.35A,0.4OHM,14@500MHZ,5.3GHZ,130-1369-000; CDS_PHYS_PART_NAME: L_0201-4NH,CERAMIC,2.5%,0.35A,0.35A,0.4OHM,14@500MHZ,5.3GHZ,130-1369-000-130-1369-000,4NH; CDS_SEC: 1; CONTINUOUS_CURRENT: 0.35A; DC_RESISTANCE: 0.4ohm; DEVICE_TYPENAME: L_0201-4NHCERAMIC25035A035A04OHM14500MHZ53GHZ130-1369-000-130-1369-0004NH; DRAWING: #NAME?; MAT: Ceramic; MAX_CURRENT: 0.35A; NV_PN: 130-1369-000; PACK_TYPE: 201; PATH: I133; PHYS_PAGE: 16; Q: 14@500MHz; ROT: 0; SEC: 1; SELF_RESONANCE_FREQ: 5.3GHz; TOL: 2.50%; VER: 1; XY: (-6650,2700)
L35 = L: ASSEMBLY: HDMI; CDS_LIB: discrete; CDS_PART_NAME: L_0201-4NH,CERAMIC,2.5%,0.35A,0.35A,0.4OHM,14@500MHZ,5.3GHZ,130-1369-000; CDS_PHYS_PART_NAME: L_0201-4NH,CERAMIC,2.5%,0.35A,0.35A,0.4OHM,14@500MHZ,5.3GHZ,130-1369-000-130-1369-000,4NH; CDS_SEC: 1; CONTINUOUS_CURRENT: 0.35A; DC_RESISTANCE: 0.4ohm; DEVICE_TYPENAME: L_0201-4NHCERAMIC25035A035A04OHM14500MHZ53GHZ130-1369-000-130-1369-0004NH; DRAWING: #NAME?; MAT: Ceramic; MAX_CURRENT: 0.35A; NV_PN: 130-1369-000; PACK_TYPE: 201; PATH: I134; PHYS_PAGE: 16; Q: 14@500MHz; ROT: 0; SEC: 1; SELF_RESONANCE_FREQ: 5.3GHz; TOL: 2.50%; VER: 1; XY: (-6650,2350)
Q11 = Q_FET_N_ENH#1: ASSEMBLY: HDMI; CDS_LIB: discrete; CDS_PART_NAME: Q_FET_N_ENH_DFN1006-DMN26D0UFB4,20V,999MOHM@10V / 3000MOHM@4.5V / 4000MOHM@2.5V,0.14A,0.805A,10V,0.35W,999NC@10V / 0NC@4.5V / A; CDS_PHYS_PART_NAME: Q_FET_N_ENH_DFN1006-DMN26D0UFB4,20V,999MOHM@10V / 3000MOHM@4.5V / 4000MOHM@2.5V,0.14A,0.805A,10V,0.35W,999NC@10V / 0NC@4.5V / B; CDS_SEC: 1; CONTINUOUS_CURRENT: 0.14A; CaptureCellPackProp: Q_FET_N_ENH##1; DEVICE_TYPENAME: Q_FET_N_ENH_DFN1006-DMN26D0UFB420V999MOHM10V3000MOHM45V4000MOHM25V014A0805A10V035W999NC10V0NC45VB; DRAWING: #NAME?; MAX_CURRENT: 0.805A; MAX_VOLTAGE: 20V; MAX_WATTAGE: 0.35W; NV_NAME: DMN26D0UFB4; NV_PN: 300-0868-000; PACK_TYPE: DFN1006; PATH: I111; PHYS_PAGE: 16; Q_G: 999nC@10V / 0nC@4.5V / 999nC@2.5V; ROT: 0; R_DS_ON: 999mohm@10V / 3000mohm@4.5V / 4000mohm@2.5V; SEC: 1; VER: 2; V_BE_GS: 10V; XY: (-9800,1150)
Q12 = Q_FET_N_ENH: ASSEMBLY: HDMI; CDS_LIB: discrete; CDS_PART_NAME: Q_FET_N_ENH_SOT363-NTJD4001N,30V,1500MOHM@10V / 1500MOHM@4.5V / 1500MOHM@2.5V,0.25A,0.25A,20V,0.272W,[ ]@10V / [ ]@4.5V / [ ]@A; CDS_PHYS_PART_NAME: Q_FET_N_ENH_SOT363-NTJD4001N,30V,1500MOHM@10V / 1500MOHM@4.5V / 1500MOHM@2.5V,0.25A,0.25A,20V,0.272W,[ ]@10V / [ ]@4.5V / [ ]@B; CDS_SEC: 2; CONTINUOUS_CURRENT: 0.25A; DEVICE_TYPENAME: Q_FET_N_ENH_SOT363-NTJD4001N30V1500MOHM10V1500MOHM45V1500MOHM25V025A025A20V0272W10V45VB; DRAWING: #NAME?; MAX_CURRENT: 0.25A; MAX_VOLTAGE: 30V; MAX_WATTAGE: 0.272W; NV_NAME: NTJD4001N; NV_PN: 300-0402-000; PACK_TYPE: SOT363; PATH: I49; PHYS_PAGE: 16; Q_G: [ ]@10V / [ ]@4.5V / [ ]@2.5V; ROT: 5; R_DS_ON: 1500mohm@10V / 1500mohm@4.5V / 1500mohm@2.5V; SEC: 2; VER: 2; V_BE_GS: 20V; XY: (-6100,6000)
Q13 = Q_FET_N_ENH#1: ASSEMBLY: HDMI; CDS_LIB: discrete; CDS_PART_NAME: Q_FET_N_ENH_DFN1006-DMN26D0UFB4,20V,999MOHM@10V / 3000MOHM@4.5V / 4000MOHM@2.5V,0.14A,0.805A,10V,0.35W,999NC@10V / 0NC@4.5V / A; CDS_PHYS_PART_NAME: Q_FET_N_ENH_DFN1006-DMN26D0UFB4,20V,999MOHM@10V / 3000MOHM@4.5V / 4000MOHM@2.5V,0.14A,0.805A,10V,0.35W,999NC@10V / 0NC@4.5V / B; CDS_SEC: 1; CONTINUOUS_CURRENT: 0.14A; CaptureCellPackProp: Q_FET_N_ENH##1; DEVICE_TYPENAME: Q_FET_N_ENH_DFN1006-DMN26D0UFB420V999MOHM10V3000MOHM45V4000MOHM25V014A0805A10V035W999NC10V0NC45VB; DRAWING: #NAME?; MAX_CURRENT: 0.805A; MAX_VOLTAGE: 20V; MAX_WATTAGE: 0.35W; NV_NAME: DMN26D0UFB4; NV_PN: 300-0868-000; PACK_TYPE: DFN1006; PATH: I50; PHYS_PAGE: 16; Q_G: 999nC@10V / 0nC@4.5V / 999nC@2.5V; ROT: 5; R_DS_ON: 999mohm@10V / 3000mohm@4.5V / 4000mohm@2.5V; SEC: 1; VER: 2; V_BE_GS: 10V; XY: (-5350,4850)
Q14 = Q_NPN: ASSEMBLY: HDMI; CDS_LIB: discrete; CDS_PART_NAME: Q_NPN_DFN1006-MMBT3904LP-7,40V,0.3V,0.2A,9999A,6V,0.25W,300-0869-000; CDS_PHYS_PART_NAME: Q_NPN_DFN1006-MMBT3904LP-7,40V,0.3V,0.2A,9999A,6V,0.25W,300-0869-000-300-0869-000; CDS_SEC: 1; CONTINUOUS_CURRENT: 0.2A; DEVICE_TYPENAME: Q_NPN_DFN1006-MMBT3904LP-740V03V02A9999A6V025W300-0869-000-300-0869-000; DRAWING: #NAME?; MAX_CURRENT: 9999A; MAX_VOLTAGE: 40V; MAX_WATTAGE: 0.25W; NV_NAME: MMBT3904LP-7; NV_PN: 300-0869-000; PACK_TYPE: DFN1006; PATH: I33; PHYS_PAGE: 16; ROT: 2; SEC: 1; VER: 1; V_BE_GS: 6V; V_CE_SAT: 0.3V; XY: (-4850,6750)
R48 = R: ASSEMBLY: HDMI; CDS_LIB: discrete; CDS_PART_NAME: R_0402-100K,1 %,62.5MW,195-0005-000; CDS_PHYS_PART_NAME: R_0402-100K,1 %,62.5MW,195-0005-000-100K,195-0005-000; CDS_SEC: 1; DEVICE_TYPENAME: R_0402-100K1625MW195-0005-000-100K195-0005-000; DRAWING: #NAME?; MAX_WATTAGE: 62.5mW; NV_PN: 195-0005-000; PATH: I101; PHYS_PAGE: 16; ROT: 0; SEC: 1; SIGNAL_MODEL: nv_res; TOL: 1%; VER: 2; XY: (-10800,4750)
R49 = R: ASSEMBLY: HDMI; CDS_LIB: discrete; CDS_PART_NAME: R_0402-100K,1 %,62.5MW,195-0005-000; CDS_PHYS_PART_NAME: R_0402-100K,1 %,62.5MW,195-0005-000-100K,195-0005-000; CDS_SEC: 1; DEVICE_TYPENAME: R_0402-100K1625MW195-0005-000-100K195-0005-000; DRAWING: #NAME?; MAX_WATTAGE: 62.5mW; NV_PN: 195-0005-000; PATH: I114; PHYS_PAGE: 16; ROT: 0; SEC: 1; SIGNAL_MODEL: nv_res; TOL: 1%; VER: 2; XY: (-10250,850)
R50 = R: ASSEMBLY: HDMI; CDS_LIB: discrete; CDS_PART_NAME: R_0402-130K,1 %,62.5MW,195-0061-000; CDS_PHYS_PART_NAME: R_0402-130K,1 %,62.5MW,195-0061-000-130K,195-0061-000; CDS_SEC: 1; DEVICE_TYPENAME: R_0402-130K1625MW195-0061-000-130K195-0061-000; DRAWING: #NAME?; MAX_WATTAGE: 62.5mW; NV_PN: 195-0061-000; PATH: I86; PHYS_PAGE: 16; ROT: 0; SEC: 1; SIGNAL_MODEL: nv_res; TOL: 1%; VER: 2; XY: (-8650,5900)
R51 = R#1: ASSEMBLY: HDMI; CDS_LIB: discrete; CDS_PART_NAME: R_0402-499OHM,1 %,62.5MW,195-0338-000; CDS_PHYS_PART_NAME: R_0402-499OHM,1 %,62.5MW,195-0338-000-195-0338-000,499OHM; CDS_SEC: 1; CHIPS_PART_NAME: R; DEVICE_TYPENAME: R_0402-499OHM1625MW195-0338-000-195-0338-000499OHM; DRAWING: #NAME?; MAX_WATTAGE: 62.5mW; NO_XNET_CONNECTION: 1; NV_PN: 195-0338-000; PATH: I76; PHYS_PAGE: 16; ROT: 0; SEC: 1; SIGNAL_MODEL: nv_res; TOL: 1%; VER: 1; XY: (-8100,1950)
R52 = R#1: ASSEMBLY: HDMI; CDS_LIB: discrete; CDS_PART_NAME: R_0402-499OHM,1 %,62.5MW,195-0338-000; CDS_PHYS_PART_NAME: R_0402-499OHM,1 %,62.5MW,195-0338-000-195-0338-000,499OHM; CDS_SEC: 1; CHIPS_PART_NAME: R; DEVICE_TYPENAME: R_0402-499OHM1625MW195-0338-000-195-0338-000499OHM; DRAWING: #NAME?; MAX_WATTAGE: 62.5mW; NO_XNET_CONNECTION: 1; NV_PN: 195-0338-000; PATH: I77; PHYS_PAGE: 16; ROT: 0; SEC: 1; SIGNAL_MODEL: nv_res; TOL: 1%; VER: 1; XY: (-8100,1850)
R53 = R#1: ASSEMBLY: HDMI; CDS_LIB: discrete; CDS_PART_NAME: R_0402-499OHM,1 %,62.5MW,195-0338-000; CDS_PHYS_PART_NAME: R_0402-499OHM,1 %,62.5MW,195-0338-000-195-0338-000,499OHM; CDS_SEC: 1; CHIPS_PART_NAME: R; DEVICE_TYPENAME: R_0402-499OHM1625MW195-0338-000-195-0338-000499OHM; DRAWING: #NAME?; MAX_WATTAGE: 62.5mW; NO_XNET_CONNECTION: 1; NV_PN: 195-0338-000; PATH: I78; PHYS_PAGE: 16; ROT: 0; SEC: 1; SIGNAL_MODEL: nv_res; TOL: 1%; VER: 1; XY: (-8100,1750)
R54 = R#1: ASSEMBLY: HDMI; CDS_LIB: discrete; CDS_PART_NAME: R_0402-499OHM,1 %,62.5MW,195-0338-000; CDS_PHYS_PART_NAME: R_0402-499OHM,1 %,62.5MW,195-0338-000-195-0338-000,499OHM; CDS_SEC: 1; CHIPS_PART_NAME: R; DEVICE_TYPENAME: R_0402-499OHM1625MW195-0338-000-195-0338-000499OHM; DRAWING: #NAME?; MAX_WATTAGE: 62.5mW; NO_XNET_CONNECTION: 1; NV_PN: 195-0338-000; PATH: I79; PHYS_PAGE: 16; ROT: 0; SEC: 1; SIGNAL_MODEL: nv_res; TOL: 1%; VER: 1; XY: (-8100,1650)
R55 = R#1: ASSEMBLY: HDMI; CDS_LIB: discrete; CDS_PART_NAME: R_0402-499OHM,1 %,62.5MW,195-0338-000; CDS_PHYS_PART_NAME: R_0402-499OHM,1 %,62.5MW,195-0338-000-195-0338-000,499OHM; CDS_SEC: 1; CHIPS_PART_NAME: R; DEVICE_TYPENAME: R_0402-499OHM1625MW195-0338-000-195-0338-000499OHM; DRAWING: #NAME?; MAX_WATTAGE: 62.5mW; NO_XNET_CONNECTION: 1; NV_PN: 195-0338-000; PATH: I80; PHYS_PAGE: 16; ROT: 0; SEC: 1; SIGNAL_MODEL: nv_res; TOL: 1%; VER: 1; XY: (-8100,1550)
R56 = R#1: ASSEMBLY: HDMI; CDS_LIB: discrete; CDS_PART_NAME: R_0402-499OHM,1 %,62.5MW,195-0338-000; CDS_PHYS_PART_NAME: R_0402-499OHM,1 %,62.5MW,195-0338-000-195-0338-000,499OHM; CDS_SEC: 1; CHIPS_PART_NAME: R; DEVICE_TYPENAME: R_0402-499OHM1625MW195-0338-000-195-0338-000499OHM; DRAWING: #NAME?; MAX_WATTAGE: 62.5mW; NO_XNET_CONNECTION: 1; NV_PN: 195-0338-000; PATH: I81; PHYS_PAGE: 16; ROT: 0; SEC: 1; SIGNAL_MODEL: nv_res; TOL: 1%; VER: 1; XY: (-8100,1450)
R57 = R#1: ASSEMBLY: HDMI; CDS_LIB: discrete; CDS_PART_NAME: R_0402-499OHM,1 %,62.5MW,195-0338-000; CDS_PHYS_PART_NAME: R_0402-499OHM,1 %,62.5MW,195-0338-000-195-0338-000,499OHM; CDS_SEC: 1; CHIPS_PART_NAME: R; DEVICE_TYPENAME: R_0402-499OHM1625MW195-0338-000-195-0338-000499OHM; DRAWING: #NAME?; MAX_WATTAGE: 62.5mW; NO_XNET_CONNECTION: 1; NV_PN: 195-0338-000; PATH: I82; PHYS_PAGE: 16; ROT: 0; SEC: 1; SIGNAL_MODEL: nv_res; TOL: 1%; VER: 1; XY: (-8100,1350)
R58 = R#1: ASSEMBLY: HDMI; CDS_LIB: discrete; CDS_PART_NAME: R_0402-499OHM,1 %,62.5MW,195-0338-000; CDS_PHYS_PART_NAME: R_0402-499OHM,1 %,62.5MW,195-0338-000-195-0338-000,499OHM; CDS_SEC: 1; CHIPS_PART_NAME: R; DEVICE_TYPENAME: R_0402-499OHM1625MW195-0338-000-195-0338-000499OHM; DRAWING: #NAME?; MAX_WATTAGE: 62.5mW; NO_XNET_CONNECTION: 1; NV_PN: 195-0338-000; PATH: I83; PHYS_PAGE: 16; ROT: 0; SEC: 1; SIGNAL_MODEL: nv_res; TOL: 1%; VER: 1; XY: (-8100,1250)
R59 = R: ASSEMBLY: HDMI; CDS_LIB: discrete; CDS_PART_NAME: R_0402-10K,5 %,62.5MW,195-0486-000; CDS_PHYS_PART_NAME: R_0402-10K,5 %,62.5MW,195-0486-000-10K,195-0486-000; CDS_SEC: 1; DEVICE_TYPENAME: R_0402-10K5625MW195-0486-000-10K195-0486-000; DRAWING: #NAME?; MAX_WATTAGE: 62.5mW; NV_PN: 195-0486-000; PATH: I55; PHYS_PAGE: 16; ROT: 2; SEC: 1; SIGNAL_MODEL: nv_res; TOL: 5%; VER: 2; XY: (-7350,6300)
R60 = R: ASSEMBLY: HDMI; CDS_LIB: discrete; CDS_PART_NAME: R_0402-10K,5 %,62.5MW,195-0486-000; CDS_PHYS_PART_NAME: R_0402-10K,5 %,62.5MW,195-0486-000-10K,195-0486-000; CDS_SEC: 1; DEVICE_TYPENAME: R_0402-10K5625MW195-0486-000-10K195-0486-000; DRAWING: #NAME?; MAX_WATTAGE: 62.5mW; NV_PN: 195-0486-000; PATH: I54; PHYS_PAGE: 16; ROT: 2; SEC: 1; SIGNAL_MODEL: nv_res; TOL: 5%; VER: 2; XY: (-6950,6300)
R61 = R#1: ASSEMBLY: HDMI; CDS_LIB: discrete; CDS_PART_NAME: R_0402-32.4K,1 %,62.5MW,195-0250-000; CDS_PHYS_PART_NAME: R_0402-32.4K,1 %,62.5MW,195-0250-000-195-0250-000,32.4K; CDS_SEC: 1; CHIPS_PART_NAME: R; DEVICE_TYPENAME: R_0402-324K1625MW195-0250-000-195-0250-000324K; DRAWING: #NAME?; MAX_WATTAGE: 62.5mW; NV_PN: 195-0250-000; PATH: I53; PHYS_PAGE: 16; ROT: 2; SEC: 1; SIGNAL_MODEL: nv_res; TOL: 1%; VER: 1; XY: (-6300,4350)
R62 = R#1: ASSEMBLY: HDMI; CDS_LIB: discrete; CDS_PART_NAME: R_0402-162K,1 %,62.5MW,195-0106-000; CDS_PHYS_PART_NAME: R_0402-162K,1 %,62.5MW,195-0106-000-162K,195-0106-000; CDS_SEC: 1; CHIPS_PART_NAME: R; DEVICE_TYPENAME: R_0402-162K1625MW195-0106-000-162K195-0106-000; DRAWING: #NAME?; MAX_WATTAGE: 62.5mW; NV_PN: 195-0106-000; PATH: I51; PHYS_PAGE: 16; ROT: 2; SEC: 1; SIGNAL_MODEL: nv_res; TOL: 1%; VER: 1; XY: (-5650,5000)
R63 = R: ASSEMBLY: HDMI; CDS_LIB: discrete; CDS_PART_NAME: R_0402-1.8K,5 %,62.5MW,195-0528-000; CDS_PHYS_PART_NAME: R_0402-1.8K,5 %,62.5MW,195-0528-000-1.8K,195-0528-000; CDS_SEC: 1; DEVICE_TYPENAME: R_0402-18K5625MW195-0528-000-18K195-0528-000; DRAWING: #NAME?; MAX_WATTAGE: 62.5mW; NV_PN: 195-0528-000; PATH: I47; PHYS_PAGE: 16; ROT: 0; SEC: 1; SIGNAL_MODEL: nv_res; TOL: 5%; VER: 2; XY: (-5550,5750)
R64 = R: ASSEMBLY: HDMI; CDS_LIB: discrete; CDS_PART_NAME: R_0402-1.8K,5 %,62.5MW,195-0528-000; CDS_PHYS_PART_NAME: R_0402-1.8K,5 %,62.5MW,195-0528-000-1.8K,195-0528-000; CDS_SEC: 1; DEVICE_TYPENAME: R_0402-18K5625MW195-0528-000-18K195-0528-000; DRAWING: #NAME?; MAX_WATTAGE: 62.5mW; NV_PN: 195-0528-000; PATH: I40; PHYS_PAGE: 16; ROT: 0; SEC: 1; SIGNAL_MODEL: nv_res; TOL: 5%; VER: 2; XY: (-5250,5750)
R65 = R: ASSEMBLY: HDMI; CDS_LIB: discrete; CDS_PART_NAME: R_0402-10K,5 %,62.5MW,195-0486-000; CDS_PHYS_PART_NAME: R_0402-10K,5 %,62.5MW,195-0486-000-10K,195-0486-000; CDS_SEC: 1; DEVICE_TYPENAME: R_0402-10K5625MW195-0486-000-10K195-0486-000; DRAWING: #NAME?; MAX_WATTAGE: 62.5mW; NV_PN: 195-0486-000; PATH: I32; PHYS_PAGE: 16; ROT: 2; SEC: 1; SIGNAL_MODEL: nv_res; TOL: 5%; VER: 2; XY: (-5100,7050)
R66 = R#1: ASSEMBLY: HDMI; CDS_LIB: discrete; CDS_PART_NAME: R_0402-5.6OHM,5 %,62.5MW,195-0609-000; CDS_PHYS_PART_NAME: R_0402-5.6OHM,5 %,62.5MW,195-0609-000-195-0609-000,5.6OHM; CDS_SEC: 1; CHIPS_PART_NAME: R; DEVICE_TYPENAME: R_0402-56OHM5625MW195-0609-000-195-0609-00056OHM; DRAWING: #NAME?; MAX_WATTAGE: 62.5mW; NV_PN: 195-0609-000; PATH: I44; PHYS_PAGE: 16; PLACEMENT_NOTE: CoLayout with L501; ROT: 0; SEC: 1; SIGNAL_MODEL: nv_res; TOL: 5%; VER: 1; XY: (-4800,4200)
R67 = R#1: ASSEMBLY: HDMI; CDS_LIB: discrete; CDS_PART_NAME: R_0402-5.6OHM,5 %,62.5MW,195-0609-000; CDS_PHYS_PART_NAME: R_0402-5.6OHM,5 %,62.5MW,195-0609-000-195-0609-000,5.6OHM; CDS_SEC: 1; CHIPS_PART_NAME: R; DEVICE_TYPENAME: R_0402-56OHM5625MW195-0609-000-195-0609-00056OHM; DRAWING: #NAME?; MAX_WATTAGE: 62.5mW; NV_PN: 195-0609-000; PATH: I2; PHYS_PAGE: 16; PLACEMENT_NOTE: CoLayout with L501; ROT: 0; SEC: 1; SIGNAL_MODEL: nv_res; TOL: 5%; VER: 1; XY: (-4800,3850)
R68 = R#1: ASSEMBLY: HDMI; CDS_LIB: discrete; CDS_PART_NAME: R_0402-5.6OHM,5 %,62.5MW,195-0609-000; CDS_PHYS_PART_NAME: R_0402-5.6OHM,5 %,62.5MW,195-0609-000-195-0609-000,5.6OHM; CDS_SEC: 1; CHIPS_PART_NAME: R; DEVICE_TYPENAME: R_0402-56OHM5625MW195-0609-000-195-0609-00056OHM; DRAWING: #NAME?; MAX_WATTAGE: 62.5mW; NV_PN: 195-0609-000; PATH: I63; PHYS_PAGE: 16; PLACEMENT_NOTE: CoLayout with L503; ROT: 0; SEC: 1; SIGNAL_MODEL: nv_res; TOL: 5%; VER: 1; XY: (-4800,3700)
R69 = R#1: ASSEMBLY: HDMI; CDS_LIB: discrete; CDS_PART_NAME: R_0402-5.6OHM,5 %,62.5MW,195-0609-000; CDS_PHYS_PART_NAME: R_0402-5.6OHM,5 %,62.5MW,195-0609-000-195-0609-000,5.6OHM; CDS_SEC: 1; CHIPS_PART_NAME: R; DEVICE_TYPENAME: R_0402-56OHM5625MW195-0609-000-195-0609-00056OHM; DRAWING: #NAME?; MAX_WATTAGE: 62.5mW; NV_PN: 195-0609-000; PATH: I65; PHYS_PAGE: 16; PLACEMENT_NOTE: CoLayout with L503; ROT: 0; SEC: 1; SIGNAL_MODEL: nv_res; TOL: 5%; VER: 1; XY: (-4800,3350)
R70 = R#1: ASSEMBLY: HDMI; CDS_LIB: discrete; CDS_PART_NAME: R_0402-5.6OHM,5 %,62.5MW,195-0609-000; CDS_PHYS_PART_NAME: R_0402-5.6OHM,5 %,62.5MW,195-0609-000-195-0609-000,5.6OHM; CDS_SEC: 1; CHIPS_PART_NAME: R; DEVICE_TYPENAME: R_0402-56OHM5625MW195-0609-000-195-0609-00056OHM; DRAWING: #NAME?; MAX_WATTAGE: 62.5mW; NV_PN: 195-0609-000; PATH: I66; PHYS_PAGE: 16; PLACEMENT_NOTE: CoLayout with L504; ROT: 0; SEC: 1; SIGNAL_MODEL: nv_res; TOL: 5%; VER: 1; XY: (-4800,3200)
R71 = R#1: ASSEMBLY: HDMI; CDS_LIB: discrete; CDS_PART_NAME: R_0402-5.6OHM,5 %,62.5MW,195-0609-000; CDS_PHYS_PART_NAME: R_0402-5.6OHM,5 %,62.5MW,195-0609-000-195-0609-000,5.6OHM; CDS_SEC: 1; CHIPS_PART_NAME: R; DEVICE_TYPENAME: R_0402-56OHM5625MW195-0609-000-195-0609-00056OHM; DRAWING: #NAME?; MAX_WATTAGE: 62.5mW; NV_PN: 195-0609-000; PATH: I68; PHYS_PAGE: 16; PLACEMENT_NOTE: CoLayout with L504; ROT: 0; SEC: 1; SIGNAL_MODEL: nv_res; TOL: 5%; VER: 1; XY: (-4800,2850)
R72 = R#1: ASSEMBLY: HDMI; CDS_LIB: discrete; CDS_PART_NAME: R_0402-5.6OHM,5 %,62.5MW,195-0609-000; CDS_PHYS_PART_NAME: R_0402-5.6OHM,5 %,62.5MW,195-0609-000-195-0609-000,5.6OHM; CDS_SEC: 1; CHIPS_PART_NAME: R; DEVICE_TYPENAME: R_0402-56OHM5625MW195-0609-000-195-0609-00056OHM; DRAWING: #NAME?; MAX_WATTAGE: 62.5mW; NV_PN: 195-0609-000; PATH: I69; PHYS_PAGE: 16; PLACEMENT_NOTE: CoLayout with L506; ROT: 0; SEC: 1; SIGNAL_MODEL: nv_res; TOL: 5%; VER: 1; XY: (-4800,2700)
R73 = R#1: ASSEMBLY: HDMI; CDS_LIB: discrete; CDS_PART_NAME: R_0402-5.6OHM,5 %,62.5MW,195-0609-000; CDS_PHYS_PART_NAME: R_0402-5.6OHM,5 %,62.5MW,195-0609-000-195-0609-000,5.6OHM; CDS_SEC: 1; CHIPS_PART_NAME: R; DEVICE_TYPENAME: R_0402-56OHM5625MW195-0609-000-195-0609-00056OHM; DRAWING: #NAME?; MAX_WATTAGE: 62.5mW; NV_PN: 195-0609-000; PATH: I71; PHYS_PAGE: 16; PLACEMENT_NOTE: CoLayout with L506; ROT: 0; SEC: 1; SIGNAL_MODEL: nv_res; TOL: 5%; VER: 1; XY: (-4800,2350)
R74 = R: ASSEMBLY: HDMI; CDS_LIB: discrete; CDS_PART_NAME: R_0402-100K,1 %,62.5MW,195-0005-000; CDS_PHYS_PART_NAME: R_0402-100K,1 %,62.5MW,195-0005-000-100K,195-0005-000; CDS_SEC: 1; DEVICE_TYPENAME: R_0402-100K1625MW195-0005-000-100K195-0005-000; DRAWING: #NAME?; MAX_WATTAGE: 62.5mW; NV_PN: 195-0005-000; PATH: I11; PHYS_PAGE: 16; ROT: 2; SEC: 1; SIGNAL_MODEL: nv_res; TOL: 1%; VER: 2; XY: (-4150,6600)
R75 = R#1: ASSEMBLY: HDMI; CDS_LIB: discrete; CDS_PART_NAME: R_0402-100K,1 %,62.5MW,195-0005-000; CDS_PHYS_PART_NAME: R_0402-100K,1 %,62.5MW,195-0005-000-100K,195-0005-000; CDS_SEC: 1; CHIPS_PART_NAME: R; DEVICE_TYPENAME: R_0402-100K1625MW195-0005-000-100K195-0005-000; DRAWING: #NAME?; MAX_WATTAGE: 62.5mW; NV_PN: 195-0005-000; PATH: I10; PHYS_PAGE: 16; ROT: 2; SEC: 1; SIGNAL_MODEL: nv_res; TOL: 1%; VER: 1; XY: (-3750,6750)
R202 = R: ASSEMBLY: HDMI; CDS_LIB: discrete; CDS_PART_NAME: R_0402-0OHM,0.05 OHM,62.5MW,195-2655-000; CDS_PHYS_PART_NAME: R_0402-0OHM,0.05 OHM,62.5MW,195-2655-000-0OHM,195-2655-000; CDS_SEC: 1; DEVICE_TYPENAME: R_0402-0OHM005OHM625MW195-2655-000-0OHM195-2655-000; DRAWING: #NAME?; MAX_WATTAGE: 62.5mW; NV_PN: 195-2655-000; PATH: I125; PHYS_PAGE: 16; ROT: 0; SEC: 1; TOL: 0.05 ohm; VER: 2; XY: (-2850,5050)
U8 = U_SW_LOAD#1: ASSEMBLY: HDMI; CDS_LIB: analog; CDS_PART_NAME: U_SW_LOAD_SOT363-GS7616SC-R,-9999V..9999V,-9999V..9999V,9999A,SWITCH,115-1566-000; CDS_PHYS_PART_NAME: U_SW_LOAD_SOT363-GS7616SC-R,-9999V..9999V,-9999V..9999V,9999A,SWITCH,115-1566-000-115-1566-000; CDS_SEC: 1; DEVICE_TYPENAME: U_SW_LOAD_SOT363-GS7616SC-R-9999V9999V-9999V9999V9999ASWITCH115-1566-000-115-1566-000; DRAWING: #NAME?; MAX_CURRENT: 9999A; MAX_VOLTAGE: -9999V..9999V; NV_NAME: GS7616SC-R; NV_PN: 115-1566-000; OUTPUT_VOLTAGE: -9999V..9999V; PACK_TYPE: SOT363; PATH: I92; PHYS_PAGE: 16; ROT: 0; SEC: 1; TYPE: Switch; VER: 4; XY: (-10150,5000)
U9 = U_PWR_SW_UL: ASSEMBLY: HDMI; CDS_LIB: power_supply; CDS_PART_NAME: U_PWR_SW_UL_SOT23_5_EFU-APL3552ABI-TRG,2.7V..5.5V,2.7V..5.5V,2A,SWITCH,315-1062-000; CDS_PHYS_PART_NAME: U_PWR_SW_UL_SOT23_5_EFU-APL3552ABI-TRG,2.7V..5.5V,2.7V..5.5V,2A,SWITCH,315-1062-000-315-1062-000; CDS_SEC: 1; DEVICE_TYPENAME: U_PWR_SW_UL_SOT23_5_EFU-APL3552ABI-TRG27V55V27V55V2ASWITCH315-1062-000-315-1062-000; DRAWING: #NAME?; FUNCTION: Power Switch; MAX_CURRENT: 2A; MAX_VOLTAGE: 2.7V..5.5V; NV_NAME: APL3552ABI-TRG; NV_PN: 315-1062-000; OUTPUT_VOLTAGE: 2.7V..5.5V; PACK_TYPE: SOT23_5_EFU; PATH: I89; PHYS_PAGE: 16; ROT: 0; SEC: 1; TYPE: Switch; VER: 1; XY: (-9450,6250)

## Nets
GND: C76.2 C77.2 C86.2 C87.2 C88.2 C89.2 C90.2 C91.2 C93.2 D14.3(GND1) D16.2 D17.2 D18.2 D19.3(GND1) D20.2 J8.2(D2_SHIELD) J8.5(D1_SHIELD) J8.8(D0_SHIELD) J8.11(CK_SHIELD) J8.17(DDC_CEC_GND) J8.40(SHIELD4) J8.41(SHIELD2) J8.42(SHIELD3) J8.43(SHIELD1) Q11.2(S) Q14.2(E) R48.2 R49.2 R50.2 R74.2 U8.4(GND) U9.2(GND) ; also on sheet 1 2 3 4 5 6 7 8 10 11 12 13 14 15 16 17 18 19 21
VDD_1V8: R65.1 ; also on sheet 2 3 4 5 8 15 19 21
VDD_3V3_HDMI: C88.1 Q11.1(G) Q12.2(G) Q12.5(G) Q13.1(G) R49.1 R59.1 R60.1 R61.2 R62.1 U8.1(VOUT1) U8.2(VOUT2) U9.4(EN)
VDD_3V3_SYS: U8.5(VIN1) U8.6(VIN2) ; also on sheet 2 3 4 5 6 7 8 12 15 16 19 20 21
VDD_5V0_HDMI_CON: C86.1 C87.1 J8.18(5V) R63.1 R64.1 U9.1(OUT)
VDD_5V_SYS: C76.1 C77.1 U9.5(IN) ; also on sheet 2 3 8 10 11 12 14 15 16 17 21
HDMI_CEC: D15.1(A1) Q13.2(S) R62.2 ; also on sheet 19
HDMI_CEC_CON: C90.1 D18.1 J8.13(CEC_HDMI) L14.2
HDMI_CEC_PU: D15.2(A2) R61.1
HDMI_CEC_Q: D15.3(CC) L14.1 Q13.3(D)
HDMI_DDC_SCL: Q12.1(S) R60.2 ; also on sheet 19
HDMI_DDC_SCL_5V0: C91.1 D17.1 J8.15(SCL) Q12.6(D) R64.2
HDMI_DDC_SDA: Q12.4(S) R59.2 ; also on sheet 19
HDMI_DDC_SDA_5V0: C89.1 D16.1 J8.16(SDA) Q12.3(D) R63.2
HDMI_HPD: Q14.3(C) R65.2 ; also on sheet 19
HDMI_HPD_CON: C93.1 D20.1 J8.19(HP_DET) R202.2
HDMI_HPD_CON_Q: Q14.1(B) R74.1 R75.2
HDMI_HPD_CON_R: R75.1 R202.1
HDMI_ILIM: R50.1 U9.3(OC*)
HDMI_TX0_N: C79.1 ; also on sheet 19
HDMI_TX0_P: C83.1 ; also on sheet 19
HDMI_TX1_N: C80.1 ; also on sheet 19
HDMI_TX1_P: C84.1 ; also on sheet 19
HDMI_TX2_N: C81.1 ; also on sheet 19
HDMI_TX2_P: C85.1 ; also on sheet 19
HDMI_TXC_CON_LC_N: C78.2 C177.1 L28.1 R51.2
HDMI_TXC_CON_LC_P: C82.2 C177.2 L29.1 R52.2
HDMI_TXC_CON_N: D14.2(2A) D14.9(2B) J8.12(CK*) R66.2
HDMI_TXC_CON_P: D14.1(1A) D14.10(1B) J8.10(CK) R67.2
HDMI_TXC_CON_R_N: C181.1 L28.2 R66.1
HDMI_TXC_CON_R_P: C181.2 L29.2 R67.1
HDMI_TXC_N: C78.1 ; also on sheet 19
HDMI_TXC_P: C82.1 ; also on sheet 19
HDMI_TXD0_CON_LC_N: C79.2 C178.1 L30.1 R53.2
HDMI_TXD0_CON_LC_P: C83.2 C178.2 L31.1 R54.2
HDMI_TXD0_CON_N: D14.4(3A) D14.7(3B) J8.9(D0*) R68.2
HDMI_TXD0_CON_P: D14.5(4A) D14.6(4B) J8.7(D0) R69.2
HDMI_TXD0_CON_R_N: C182.1 L30.2 R68.1
HDMI_TXD0_CON_R_P: C182.2 L31.2 R69.1
HDMI_TXD1_CON_LC_N: C80.2 C179.1 L32.1 R55.2
HDMI_TXD1_CON_LC_P: C84.2 C179.2 L33.1 R56.2
HDMI_TXD1_CON_N: D19.5(4A) D19.6(4B) J8.6(D1*) R70.2
HDMI_TXD1_CON_P: D19.4(3A) D19.7(3B) J8.4(D1) R71.2
HDMI_TXD1_CON_R_N: C183.1 L32.2 R70.1
HDMI_TXD1_CON_R_P: C183.2 L33.2 R71.1
HDMI_TXD2_CON_LC_N: C81.2 C180.1 L34.1 R57.2
HDMI_TXD2_CON_LC_P: C85.2 C180.2 L35.1 R58.2
HDMI_TXD2_CON_N: D19.1(1A) D19.10(1B) J8.3(D2*) R72.2
HDMI_TXD2_CON_P: D19.2(2A) D19.9(2B) J8.1(D2) R73.2
HDMI_TXD2_CON_R_N: C184.1 L34.2 R72.1
HDMI_TXD2_CON_R_P: C184.2 L35.2 R73.1
IFP_TERM: Q11.3(D) R51.1 R52.1 R53.1 R54.1 R55.1 R56.1 R57.1 R58.1
MOD_SLEEP*: R48.1 U8.3(EN) ; also on sheet 2 21
SNN_HDMI_RES1: J8.14(RESERVED)

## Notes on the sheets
sheet 9
- A
- B
- C
- D
- E
- F
- G
- H
- HDMI Connector
- PLACE NEAR HDMI CON
- 1
- 1
- MINIMUM 200MA
- FOR HDMI TO VGA
- DONGLE
- 2
- 2
- 3
- 3
- 4
- 4
- 5
- HDMI ESD, CLOSE TO INPUT CONNECTOR
- 5
- NVIDIA CORPORATION
- 2701 SAN TOMAS
  EXPRESSWAY
- ASSEMBLY
- <ASSEMBLY_DESCRIPTION>
- SANTA CLARA, CA 95050, USA
- PAGE DETAIL
- HDMI
- NV_PN
- 600-13509-BASE-100
- ALL NVIDIA DESIGN SPECIFICATIONS, REFERENCE SPECIFICATIONS, REFERENCE BOARDS, FILES, DRAWINGS, DIAGNOSTICS, LISTS AND OTHER DOCUMENTS OR INFORMATION (TOGETHER AND SEPARATELY, 'MATERIALS') ARE BEING PROVIDED 'AS IS'. THE MATERIALS
  MAY
- CONTAIN KNOWN AND UNKNOWN VIOLATIONS OR DEVIATIONS OF INDUSTRY STANDARDS AND SPECIFICATIONS. NVIDIA MAKES NO WARRANTIES, EXPRESSED, IMPLIED, STATUTORY OR OTHERWISE WITH RESPECT TO THE MATERIALS OR OTHERWISE, AND EXPRESSLY DISCLAIMS
  ALL
- PCB REV
- P3509-A01
- PAGE
- 16 OF 25
- IMPLIED WARRANTIES INCLUDING, WITHOUT LIMITATION, THE WARRANTIES OF DESIGN, OF NONINFRINGEMENT, MERCHANTABILITY OR FITNESS FOR A PARTICULAR PURPOSE, OR ARISING FROM A COURSE OF DEALING, TRADE USAGE, TRADE PRACTICE, OR INDUSTRY
  STANDARDS.
- BOM REV
- <BOM_REV>
- DATE
- 27-NOV-2019
- A
- B
- C
- D
- E
- F
- G
- H
